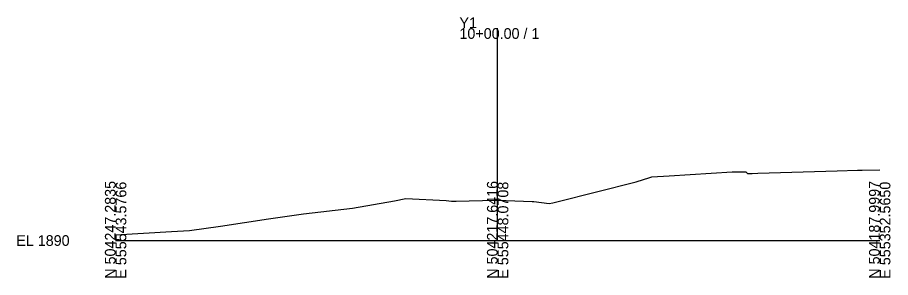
# Model space of a CAD drawing. Extents: x -26 to 203, y -10 to 5015.
# Drawn here: x -25.7 to 202.8, y -9.7 to 58.4 of the extents above; entities that cross this region are included whole.
import ezdxf

# ---------------------------------------------------------------- set-up
doc = ezdxf.new("R2010")
doc.units = 0
doc.layers.add('Exist Cross Section Cell', color=7, linetype='Continuous')
doc.layers.add('Exist XS Ground Line', color=7, linetype='Continuous')

msp = doc.modelspace()

# ---------------------------------------------------------------- linework, layer by layer
at = {"layer": 'Exist Cross Section Cell'}
for p, q in [((100, 0), (100, 55.61)), ((0, 0), (100, 0)), ((100, 0), (200, 0))]:
    msp.add_line(p, q, dxfattribs=at)
at = {"layer": 'Exist XS Ground Line'}
for p, q in [((188.85, 18.21), (194.18, 18.41)), ((194.18, 18.41), (195.4, 18.43)), ((195.4, 18.43), (200, 18.54)), ((136.22, 15.38), (139.8, 16.54)), ((139.8, 16.54), (140.32, 16.69)), ((140.32, 16.69), (144.93, 16.9)), ((144.93, 16.9), (161.38, 17.98)), ((161.38, 17.98), (164.98, 18.01)), ((164.98, 18.01), (165.4, 17.52)), ((165.4, 17.52), (166.65, 17.54)), ((166.65, 17.54), (168.11, 17.63)), ((168.11, 17.63), (188.85, 18.21)), ((115.52, 10.11), (136.22, 15.38)), ((62.04, 8.49), (72.97, 10.39)), ((72.97, 10.39), (75.94, 11.03)), ((75.94, 11.03), (86.5, 10.45)), ((86.5, 10.45), (87.96, 10.31)), ((87.96, 10.31), (88.78, 10.29)), ((88.78, 10.29), (89.11, 10.3)), ((89.11, 10.3), (99.41, 10.56)), ((99.41, 10.56), (100, 10.54)), ((100, 10.54), (109.04, 10.26)), ((109.04, 10.26), (109.43, 10.2)), ((109.43, 10.2), (113.51, 9.66)), ((113.51, 9.66), (114.41, 9.84)), ((114.41, 9.84), (115.52, 10.11)), ((40, 5.71), (49.19, 7.03)), ((49.19, 7.03), (62.04, 8.49)), ((27.48, 3.79), (40, 5.71)), ((0, 1.48), (14.62, 2.36)), ((14.62, 2.36), (19.38, 2.66)), ((19.38, 2.66), (27.48, 3.79))]:
    msp.add_line(p, q, dxfattribs=at)

# ---------------------------------------------------------------- texts
at = {"layer": 'Exist Cross Section Cell'}
for s, p in [('Y1', (90, 55.61)), ('10+00.00 / 1', (90, 52.81)), ('EL 1890', (-26, -1.4))]:
    msp.add_text(s, height=2.8, dxfattribs=at).set_placement(p)
for s, p in [('N 504247.2835', (0, -10)), ('E 555543.5766', (2.8, -10)), ('N 504217.6416', (100, -10)), ('E 555448.0708', (102.8, -10)), ('N 504187.9997', (200, -10)), ('E 555352.5650', (202.8, -10))]:
    msp.add_text(s, height=2.8, rotation=90, dxfattribs=at).set_placement(p)

doc.saveas('drawing.dxf')
